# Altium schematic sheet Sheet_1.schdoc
size 292 x 204 mm; Device: A_A4; Symbol: A_A4; Name: A_A4; @Project Name: Roborock fan driver with tacho frequency divider; REV: 1.0; Date: 2024-04-24; Sheet: 1/1; Draw By: David Buezas; Company: Your Company; Convert to PCB: yes; Add into BOM: yes; @Page No: 1; @Page Count: 1; @Schematic Name: Schematic; @Board Name: Disk shape; @Update Date: 2025-03-11; @Create Time: 19:24:59; @Update Time: 20:35:54; @Page Name: Sheet_1; @Create Date: 2025-03-04
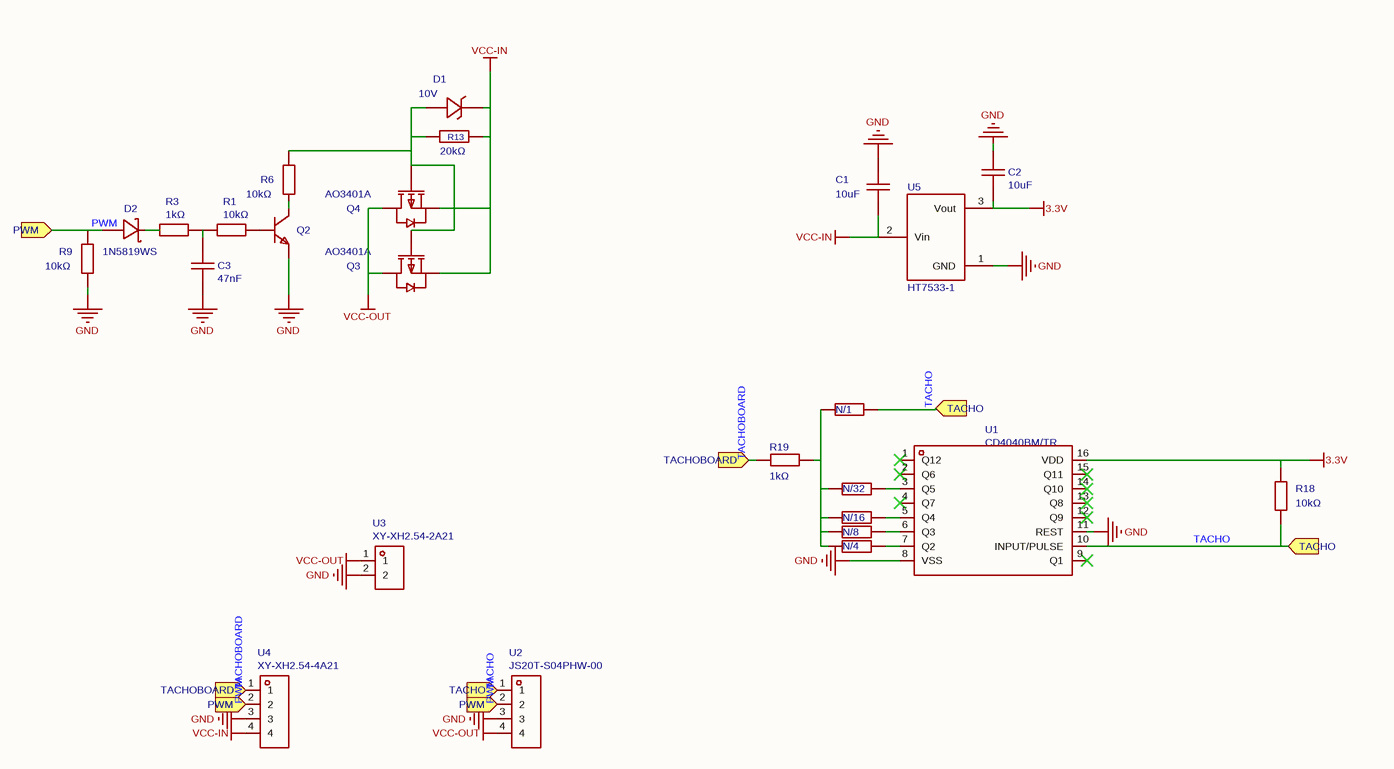
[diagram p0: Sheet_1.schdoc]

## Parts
C1  10uF  [C0805]
C2  10uF  [C0603]
C3  47nF  [C0603]
D1  Zener Voltage(Nom): 10V  [SOD-123_L2.7-W1.6-LS3.7-RD]  (hidden comment: MMSZ5240B)
D2  1N5819WS  [SOD-323_L1.8-W1.3-LS2.5-RD]
Q2  SS8050(RANGE:200-350)  [SOT-23-3_L2.9-W1.3-P1.90-LS2.4-BR]  (value not drawn)
Q3  AO3401A  [SOT-23_L2.9-W1.3-P1.90-LS2.4-BR]
Q4  AO3401A  [SOT-23_L2.9-W1.3-P1.90-LS2.4-BR]
R1  10kΩ  [R0603]
R3  1kΩ  [R0603]
R6  10kΩ  [R0603]
R8  N/16  [R0603]
R9  10kΩ  [R0603]
R13  20kΩ  [R0603]
R14  N/32  [R0603]
R15  N/4  [R0603]
R16  N/8  [R0603]
R17  N/1  [R0603]
R18  10kΩ  [R0603]
R19  1kΩ  [R0603]
U1  CD4040BM/TR  [SOP-16_L9.9-W3.9-P1.27-LS6.0-BL]
U2  JS20T-S04PHW-00  [CONN-TH_4P-P2.00_JS20T-S04PHW-00]
U3  XY-XH2.54-2A21  [HDR-TH_2P-P2.50_XY-XH2.54-2A21]
U4  XY-XH2.54-4A21  [HDR-TH_4P-P2.50-H-F-W7.0-N]
U5  HT7533-1  [SOT-89-3_L4.5-W2.5-P1.50-LS4.2-BR]

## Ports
PWM (in), TACHO (in), TACHOBOARD (in)

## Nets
3.3V: C2.1 R18.2 U1.16(VDD) U5.3(Vout)
GND: C1.2 C2.2 C3.1 Q2.2(E) R9.1 U1.8(VSS) U1.11(REST) U2.3 U3.2 U4.3 U5.1(GND)
VCC-IN: C1.1 D1.1(K) Q3.2(S) Q4.2(S) R13.2 U4.4 U5.2(Vin)
VCC-OUT: Q3.3(D) Q4.3(D) U2.4 U3.1
PWM: D2.2(A) R9.2 U2.2 U4.2 ; port PWM
TACHO: R17.1 R18.1 U1.10(INPUT/PULSE) U2.1 ; port TACHO
TACHOBOARD: R19.2 U4.1 ; port TACHOBOARD
NetC3_2: C3.2 R1.1 R3.2
NetD1_2: D1.2(A) Q3.1(G) Q4.1(G) R6.2 R13.1
NetD2_1: D2.1(K) R3.1
NetQ2_1: Q2.1(B) R1.2
NetQ2_3: Q2.3(C) R6.1
NetR8_1: R8.1 R14.1 R15.1 R16.2 R17.2 R19.1
NetR8_2: R8.2 U1.5(Q4)
NetR14_2: R14.2 U1.3(Q5)
NetR15_2: R15.2 U1.7(Q2)
NetR16_1: R16.1 U1.6(Q3)

Not connected (* = marked no-connect by the designer): U1 1(Q12)* 2(Q6)* 4(Q7)* 9(Q1)* 12(Q9)* 13(Q8)* 14(Q10)* 15(Q11)*

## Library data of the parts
C1 = GRM21BR61H106KE43L: Capacitance: Tolerance:±10% Tolerance:±10% Voltage Rated: Temperature Coefficient:; Manufacturer: muRata(村田); Symbol: CL10A105KB8NNNC; Convert to PCB: yes; ModelId: 8c88e81f49c6409b980720ec8953afb6; ModelName: C0805_L2.0-W1.3-H1.3; ModelTransform: 78.74,51.181,0,0,0,0,0,0.0005,0; Tolerance: ±10%
C2 = CL10A106KP8NNNC: Capacitance: Tolerance:±10% Tolerance:±10% Voltage Rated: Temperature Coefficient:; Manufacturer: SAMSUNG(三星); Symbol: CL05A105KA5NQNC; Convert to PCB: yes; ModelId: 624118aa3cc7497086c383c2d72e0852; ModelName: C0603_L1.6-W0.8-H0.8; ModelTransform: 62.992,31.496,0,0,0,0,0,0,0; Tolerance: ±10%
C3 = CL10B473KB8NNNC: Capacitance: Tolerance:±10% Tolerance:±10% Voltage Rated: Temperature Coefficient:; Manufacturer: SAMSUNG(三星); Symbol: CL05A105KA5NQNC; Convert to PCB: yes; ModelId: 624118aa3cc7497086c383c2d72e0852; ModelName: C0603_L1.6-W0.8-H0.8; ModelTransform: 62.992,31.496,0,0,0,0,0,0,0; Tolerance: ±10%
D1 = MMSZ5240B_C19077425: Diode Configuration:Independent Type Zener Voltage(Nom):10V Reverse Leakage Current (Ir):3uA@8V Zener Voltage(Range):9.5V~10.5V Zener Voltage(Range):9.5V~10.5V Pd - Power Dissipation(Pd):500mW Impedance(Zzt):17Ω; Manufacturer: 宏嘉诚; Convert to PCB: yes; ModelId: 31ae3d5c025440ebafdeabfabec0ebeb; ModelName: SOD-123_L2.7-W1.6-H1.4-LS3.7; ModelTransform: 146.026,62.992,0,180,0,0,0.0005,0,0; Reverse Leakage Current (Ir): 3uA@8V; Pd - Power Dissipation(Pd): 500mW; Impedance(Zzt): 17Ω
D2 = 1N5819WS_C191023: Forward Voltage (Vf@If):600mV@1A Reverse Voltage (Vr):40V Rectified Current:1A; Manufacturer: Hottech(合科泰); Convert to PCB: yes; ModelId: 7a4b9b6e725448df9ee2451185154c27; ModelName: SOD-323_L1.7-W1.3-H1.1-LS2.5; ModelTransform: 98.91933,51.181,0,180,0,0,0.985,-0.0005,0; Reverse Voltage (Vr): 40V; Rectified Current: 1A
Q2 = SS8050(RANGE:200-350)_C2150: Transistor Type: Collector Current (Ic): Collector-Emitter Breakdown Voltage (Vceo): Power Dissipation (Pd): DC Current Gain (hFE@Ic,Vce):200@800mA,1V DC Current Gain (hFE@Ic,Vce):200@800mA,1V Transition Frequency (fT):100MHz Collector Cut-Off Current (Ic; Manufacturer: CJ(江苏长电/长晶); Symbol: SS8050_C2150; Convert to PCB: yes; ModelId: 62a57c6760504a01965db6419a6d07df; ModelName: SOT-23-3P_L2.9-W1.3-H1.0-LS2.4-P0.95; ModelTransform: 98.425,114.173,0,180,0,0,0.0005,-0.0005,0; Transition Frequency (fT): 100MHz; Collector Cut-Off Current (Icbo): 100nA; Collector-Emitter Saturation Voltage (VCE(sat)@Ic,Ib): 500mV@800mA,80mA
Q3 Q4 = AO3401A_C15127: Type:1 Piece P-Channel Drain Source Voltage (Vdss): Continuous Drain Current (Id): Drain Source On Resistance (RDS(on)@Vgs,Id):44mΩ@10V,4.3A Power Dissipation (Pd): Gate Threshold Voltage (Vgs(th)@Id):1.3V@250uA Total Gate Charge (Qg@Vgs):12.2nC@4.5V Inpu; Manufacturer: AOS; AddInBom: yes; ModelId: 62a57c6760504a01965db6419a6d07df; ModelName: SOT-23-3P_L2.9-W1.3-H1.0-LS2.4-P0.95; ModelTransform: 98.64468,114.173,0,180,0,0,0,0,0; Input Capacitance (Ciss@Vds): 1.2nF@15V
R1 R6 R9 R18 = 0603WAF1002T5E: Type:Thick Film Resistors Resistance:10kΩ Tolerance:±1% Tolerance:±1% Power(Watts): Overload Voltage (Max): Temperature Coefficient:±100ppm/℃ Temperature Coefficient:±100ppm/℃ Operating Temperature Range:-55℃~+155℃ Operating Temperature Range:-55℃~+155℃; Manufacturer: UNI-ROYAL(厚声); Convert to PCB: yes; ModelId: 112863783b5b41f1b5254f87eedc7932; ModelTransform: 31.8897,63.7794,0,90,0,0,0,0,0; Tolerance: ±1%
R3 = 0603WAF1001T5E: Type:Thick Film Resistors Resistance:1kΩ Tolerance:±1% Tolerance:±1% Power(Watts): Overload Voltage (Max): Temperature Coefficient:±100ppm/℃ Temperature Coefficient:±100ppm/℃ Operating Temperature Range:-55℃~+155℃ Operating Temperature Range:-55℃~+155℃; Manufacturer: UNI-ROYAL(厚声); Convert to PCB: yes; ModelId: 112863783b5b41f1b5254f87eedc7932; ModelTransform: 31.8897,63.7794,0,90,0,0,0,0,0; Tolerance: ±1%
R8 = 0603WAF0000T5E: Type:Thick Film Resistors Resistance: Tolerance:±1% Tolerance:±1% Power(Watts): Overload Voltage (Max): Operating Temperature Range:-55℃~+155℃ Operating Temperature Range:-55℃~+155℃; Manufacturer: UNI-ROYAL(厚声); AddInBom: yes; ModelId: 112863783b5b41f1b5254f87eedc7932; ModelTransform: 31.8897,63.7794,0,90,0,0,0,0,0; Value: 0Ω; Tolerance: ±1%
R13 = 0603WAF2002T5E: Type:Thick Film Resistors Resistance:20kΩ Tolerance:±1% Tolerance:±1% Power(Watts): Overload Voltage (Max): Temperature Coefficient:±100ppm/℃ Temperature Coefficient:±100ppm/℃ Operating Temperature Range:-55℃~+155℃ Operating Temperature Range:-55℃~+155℃; Manufacturer: UNI-ROYAL(厚声); AddInBom: yes; ModelId: 112863783b5b41f1b5254f87eedc7932; ModelTransform: 31.8897,63.7794,0,90,0,0,0,0,0; Tolerance: ±1%
R14-R17 = 0603WAF0000T5E: Type:Thick Film Resistors Resistance: Tolerance:±1% Tolerance:±1% Power(Watts): Overload Voltage (Max): Operating Temperature Range:-55℃~+155℃ Operating Temperature Range:-55℃~+155℃; Manufacturer: UNI-ROYAL(厚声); Add into BOM: no; ConvertToPcb: yes; ModelId: 112863783b5b41f1b5254f87eedc7932; ModelTransform: 31.8897,63.7794,0,90,0,0,0,0,0; Value: 0Ω; Tolerance: ±1%
R19 = 0603WAF1001T5E: Type:Thick Film Resistors Resistance:1kΩ Tolerance:±1% Tolerance:±1% Power(Watts): Overload Voltage (Max): Temperature Coefficient:±100ppm/℃ Temperature Coefficient:±100ppm/℃ Operating Temperature Range:-55℃~+155℃ Operating Temperature Range:-55℃~+155℃; Manufacturer: UNI-ROYAL(厚声); Symbol: 0603WAF1002T5E; Convert to PCB: yes; ModelId: 112863783b5b41f1b5254f87eedc7932; ModelTransform: 31.8897,63.7794,0,90,0,0,0,0,0; Tolerance: ±1%
U1 = CD4040BM/TR: Manufacturer: HGSEMI(华冠); Convert to PCB: yes; ModelId: 2f91ac34cbab4a3da9c51136f871f91e; ModelTransform: 389.763,236.22,0,0,0,0,0,0,0
U2 = JS20T-S04PHW-00: Pins Structure:1x4P Pitch:2mm Mounting Style:Bend insert Reference Series:PH Number of Pins:4P Number of Rows:1 Number of PINs Per Row:4 Contact Material:Brass; Manufacturer: JS(钜硕电子); Convert to PCB: yes; Pins Structure: 1x4P; Pitch: 2mm; Reference Series: PH; Number of PINs Per Row: 4
U3 = XY-XH2.54-2A21: Pins Structure:1x2P Pitch:2.54mm Mounting Style:Right-Angle Number of Pins:2P Number of Rows:1 Number of PINs Per Row:2 Row Spacing:2.54mm Current Rating (Max):3A Operating Temperature Range:-25℃~+85℃ Operating Temperature Range:-25℃~+85℃; Manufacturer: XYECONN(辛译); Convert to PCB: yes; ModelId: 4f55794a7f6d4c02ad94053a5a9383dc; ModelTransform: 295.314,301.1805,0,0,0,0,0,-139.37,-133.858; Pins Structure: 1x2P; Pitch: 2.54mm; Number of PINs Per Row: 2; Current Rating (Max): 3A
U4 = XY-XH2.54-4A21: Pins Structure:1x4P Pitch:2.54mm Mounting Style:Right-Angle Number of Pins:4P Number of Rows:1 Number of PINs Per Row:4 Row Spacing:2.54mm Current Rating (Max):3A Operating Temperature Range:-25℃~+85℃ Operating Temperature Range:-25℃~+85℃; Manufacturer: XYECONN(辛译); Convert to PCB: yes; ModelId: 6adf6b120b0c49b795c7b95dcd3314aa; ModelTransform: 492.5187,301.968,0,0,0,0,-0.005,-137.795,-133.858; Pins Structure: 1x4P; Pitch: 2.54mm; Number of PINs Per Row: 4; Current Rating (Max): 3A
U5 = HT7533-1_C14289: Output Type:Fixed Voltage - Supply:30V Output Voltage:3.3V Output Voltage:3.3V Output Current:100mA Power Supply Rejection Ratio (PSRR):- Voltage Dropout:55mV@(1mA) standby current:- Output Configuration:Positive electrode Number of Outputs:1; Manufacturer: HOLTEK(合泰/盛群); Convert to PCB: yes; ModelId: 78d1c457a54a48a6982859ae8b9fc42d; ModelName: SOT-89-3_L4.3-W2.5-H1.6-LS4.1-P1.50; ModelTransform: 161.417,169.291,0,180,0,0,-11.808,0,0; Output Type: Fixed; Voltage - Supply: 30V; Output Voltage: 3.3V; Output Current: 100mA; Number of Outputs: 1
